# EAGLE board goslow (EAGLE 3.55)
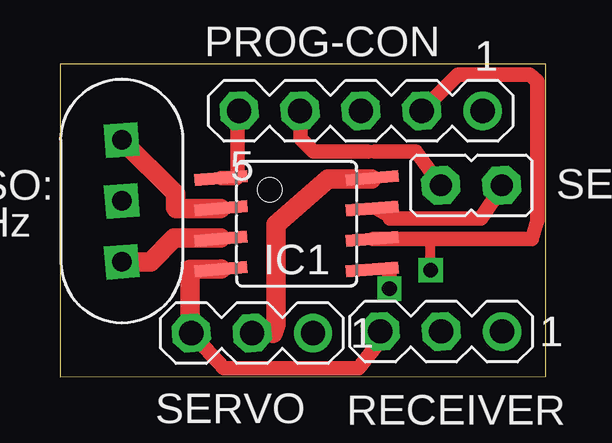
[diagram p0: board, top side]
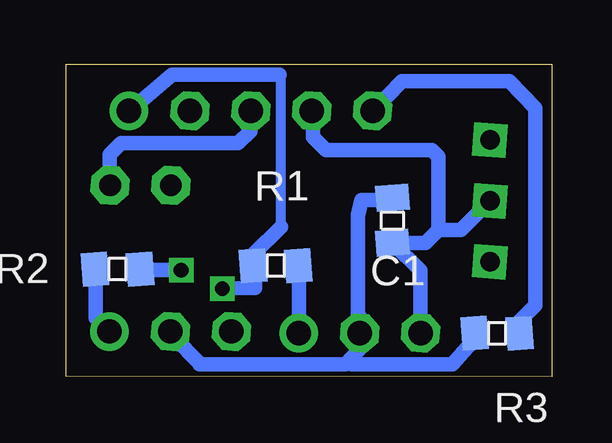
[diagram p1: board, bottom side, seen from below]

Size 20.26 x 13.04 mm. Coordinates in mm from the lower left corner, seen from the top.
Outline: 0,0 20.26,0.01 20.26,13.02 0,13.04 0,0
Copper layers used: Top, Bottom

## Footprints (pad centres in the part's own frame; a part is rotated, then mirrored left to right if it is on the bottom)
05 = smd 1.092 x 1.397 rotated 4.4:  0.94,0 | smd 1.092 x 1.397 rotated 4.3:  -0.94,0
P-8 = smd 0.5 x 2.2 rotated 4.3:  -1.905,-3.154 | smd 0.5 x 2.2 rotated 4.4:  -0.645,-3.154 | smd 0.5 x 2.2 rotated 4.5:  0.625,-3.154 | smd 0.5 x 2.2 rotated 4.6:  1.895,-3.154 | smd 0.5 x 2.2 rotated 4.9:  -1.905,3.154 | smd 0.5 x 2.2 rotated 4.8:  -0.635,3.154 | smd 0.5 x 2.2 rotated 4.7:  0.635,3.154;  1.905,3.154
05-1 = drill 1.016 pad 1.6 round:  -5.08,0 | drill 1.016 pad 1.6 octagon:  -2.54,0;  0,0;  2.54,0;  5.08,0
03-1 = drill 1.016 pad 1.6 round:  -2.54,0 | drill 1.016 pad 1.6 octagon:  0,0;  2.54,0
SON-V = drill 0.813 pad 1.397 square:  0,2.54;  0,0;  0,-2.54
1 = drill 0.914 pad 1.6 octagon:  0,-1.27;  0,1.27

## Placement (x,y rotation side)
C1  100n  [05]  6.65,6.52 90 bottom
IC1  90S2323-S  [P-8]  9.87,6.38 270 top
PROG-CON  con3  [05-1]  12.55,11.09 180 top
R1  1k  [05]  11.52,4.63 0 bottom
R2  1k  [05]  18.11,4.49 180 bottom
R3  1k  [05]  2.28,1.8 180 bottom
RECEIVER  con2  [03-1]  15.9,1.88 180 top
RESO:  4MHz  [SON-V]  2.58,7.33 0 top
SERVO  con1  [03-1]  8.01,1.82 180 top
SETUP  JP1E  [1]  17.16,7.98 90 top

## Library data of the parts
C1 R1-R3 = smd
IC1 = AT90SMCU
PROG-CON RECEIVER SERVO = con-lstb
RESO: = hans
SETUP = jumps

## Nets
GND: C1. IC1. PROG-CON. RECEIVER. RESO:. SERVO. SETUP.
N$1: IC1. RESO:.
N$2: IC1. RESO:.
N$3: C1. IC1. R3. RECEIVER. SERVO.
N$4: IC1. PROG-CON. R3.
N$6: IC1. PROG-CON. R1.
N$9: R1. SERVO.
N$10: R2. RECEIVER.
N$12: IC1. PROG-CON. SETUP.
N$13: IC1. PROG-CON. R2.

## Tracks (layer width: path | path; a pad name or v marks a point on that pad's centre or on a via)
GND  (via drill 0.61 pad 1.02)
  Top 0.406: 5.42,1.8 5.46,1.8 SERVO. v5.49,1.8 | 13.33,1.85 RECEIVER. | 12.85,9.39 13.14,9.39 | v5.49,1.8 | v5.49,1.8 | v5.49,1.8 5.46,1.77 5.52,1.77
  Top 0.61: 13.33,1.85 13.33,1.46 12.44,0.34 6.85,0.34 5.52,1.77 | SETUP. 14.85,9.39 13.14,9.39 | 12.85,9.39 10.57,9.39 10.03,9.93 10.03,11.11 10,11.11 9.99,11.1 10,11.09 10.01,11.09
  Top 0.813: 6.71,4.48 5.42,4.46 5.42,1.8
  Bottom 0.406: 9.96,11.04 10.01,11.09 | C1.
  Bottom 0.61: 9.96,11.04 9.96,10 9.42,9.46 5.01,9.46 4.73,9.17 4.73,6.12 | 4.73,6.12 5.26,5.58 C1. | 2.58,7.33 3.79,6.12 4.73,6.12 | C1. 5.49,4.42 v5.49,1.8
N$1
  Top 0.406: 6.69,5.77 6.71,5.75 | RESO:. 2.57,4.79 | RESO:.
  Top 0.813: 6.69,5.77 4.76,5.77 3.77,4.79 RESO:.
N$2
  Top 0.406: 6.7,7.01 6.71,7.02 | 4.82,7.04 4.85,7.01
  Top 0.813: 2.58,9.87 4.82,7.63 4.82,7.04 | 4.85,7.01 6.7,7.01
N$3  (via drill 0.61 pad 1.02)
  Top 0.406: 12.99,8.25 13.02,8.28 | v8.03,1.8 | 8.01,1.82 v8.03,1.8
  Top 0.61: 8.88,1.8 v8.03,1.8 v8.03,1.74 8.03,1.68 8.01,1.66
  Top 0.813: 12.99,8.25 11.17,8.25 9.01,6.34 9.01,2.19 8.88,1.8
  Bottom 0.406: 6.74,7.36 6.65,7.46 | 14.69,0.5 14.58,0.51 | 8.03,2.53 8.09,2.6 | 3.22,1.8 3.22,1.56 | 8.6,0.5 8.54,0.5 8.5,0.47 8.34,0.5
  Bottom 0.61: 6.74,7.36 7.93,7.36 8.09,6.73 8.09,2.6 | 14.69,0.5 8.6,0.5 8.03,1.14 v8.03,1.74 v8.03,1.8 8.03,2.53 | 3.22,1.56 4.15,0.5 8.34,0.5 | 15.9,1.88 15.9,1.81 15.91,1.81 15.81,1.71 15.82,1.7 14.64,0.51 14.58,0.51
N$4
  Top 0.406: 7.42,11.11 7.46,11.11 PROG-CON.
  Top 0.61: 6.71,8.28 7.37,8.28 7.41,8.32 7.41,11 7.46,11.05 7.42,11.09 7.42,11.11
  Bottom 0.406: R3. 1.34,2.33
  Bottom 0.61: 1.34,2.33 0.69,2.98 0.69,11.2 1.77,12.31 6.25,12.31 7.46,11.08 7.58,11.08 7.6,11.09 | 7.61,11.1 7.6,11.09 | 7.6,11.09 PROG-CON.
N$6  (via drill 0.61 pad 1.02)
  Top 0.406: IC1. 13.01,4.46 13.01,4.44 13.62,4.44 13.74,4.31
  Top 0.61: 13.74,4.31 v13.74,3.67
  Bottom 0.406: 17.65,11.2 17.63,11.09 | 17.55,11.14 17.65,11.08 | 11.36,12.6 11.3,12.41 11.3,6.25 | 12.41,4.58 12.41,4.53 12.38,4.5 | 12.41,4.58 R1. | 12.41,4.58 12.41,5.14
  Bottom 0.61: 17.65,11.08 17.65,11.2 | 17.55,11.14 15.84,12.6 11.36,12.6 | 12.41,5.14 11.3,6.25 | 12.38,4.5 12.38,3.71 v13.74,3.67
N$9
  Bottom 0.406: 10.54,4.59 10.58,4.63 | 10.54,1.84
  Bottom 0.61: 10.55,1.82 10.54,1.84 10.54,4.59
N$10
  Bottom 0.406: 18.47,1.85 18.44,1.88 18.39,1.84 | 19.01,4.45 19.05,4.49 | 18.39,1.84 18.38,1.84 | 18.39,1.84 18.41,1.84
  Bottom 0.61: 19.01,4.45 19.01,2.44 18.41,1.84
N$12  (via drill 0.61 pad 1.02)
  Top 0.406: 12.99,6.98 13.02,7.01 13.75,6.6 | 18.44,7.93 v18.44,7.96 | v18.44,7.96 | v18.44,7.96 18.43,7.98
  Top 0.61: 13.75,6.6 17.55,6.6 18.44,7.93
  Bottom 0.406: 12.57,11.11 12.55,11.09
  Bottom 0.61: v18.44,7.96 18.44,9.27 17.96,9.74 13.08,9.74 12.57,10.25 12.57,11.11
N$13  (via drill 0.61 pad 1.02)
  Top 0.406: 13.04,5.74 13.01,5.75 13.02,5.74 | v15.46,4.44 15.42,4.47 15.42,5.77 16.63,5.77 16.69,5.74
  Top 0.61: 15.09,11.09 16.6,12.6 19.58,12.6 19.9,12.31 19.9,6.5 19.68,5.74 17.36,5.74 16.69,5.74 13.04,5.74
  Bottom 0.406: 17.12,4.44 R2.
  Bottom 0.61: v15.46,4.44 17.12,4.44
